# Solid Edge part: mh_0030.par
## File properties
Title: holder_handle_f
Author: edge
Template: normal.par
Last saved by: edge
Revision: 25
Application: Solid Edge
Material: ＡＢＳ
非切断部品: False
文書内容のタイプ: 0
Density: 0.001200 g/mm^3
Accuracy: 0.99
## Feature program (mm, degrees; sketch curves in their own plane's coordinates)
sketch for "unnamed Protrusion 1" plane through (0, 0, 0) normal (0, 0, 1) x-axis (1, 0, 0)
  line (-45, 0) -> (45, 0)
  line (45, 0) -> (45, -120)
  line (45, -120) -> (-45, -120)
  line (-45, -120) -> (-45, 0)
extrude "unnamed Protrusion 1" add finite 9 along +normal
thinwall "Thinwall_1"  Thickness = 1 mm
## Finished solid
Body 1: solid body, 11 faces, 24 edges, 16 vertices.
  Faces by surface: plane 11
  Edges by curve: line 24
Bounding box of the edges (mm): 90.000 x 120.000 x 9.000, from (-45, -120, 0) to (45, 0, 9).
Planar faces by outward normal: +x 2, +y 2, +z 1, -x 2, -y 2, -z 2
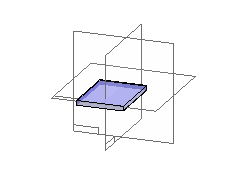
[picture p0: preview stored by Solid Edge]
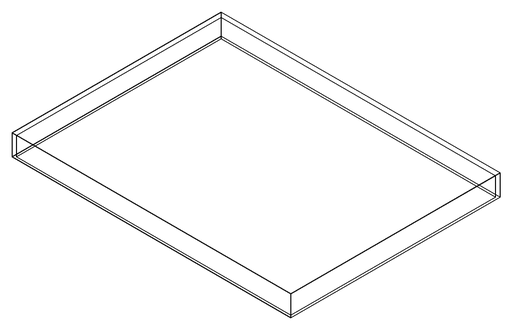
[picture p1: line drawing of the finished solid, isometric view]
